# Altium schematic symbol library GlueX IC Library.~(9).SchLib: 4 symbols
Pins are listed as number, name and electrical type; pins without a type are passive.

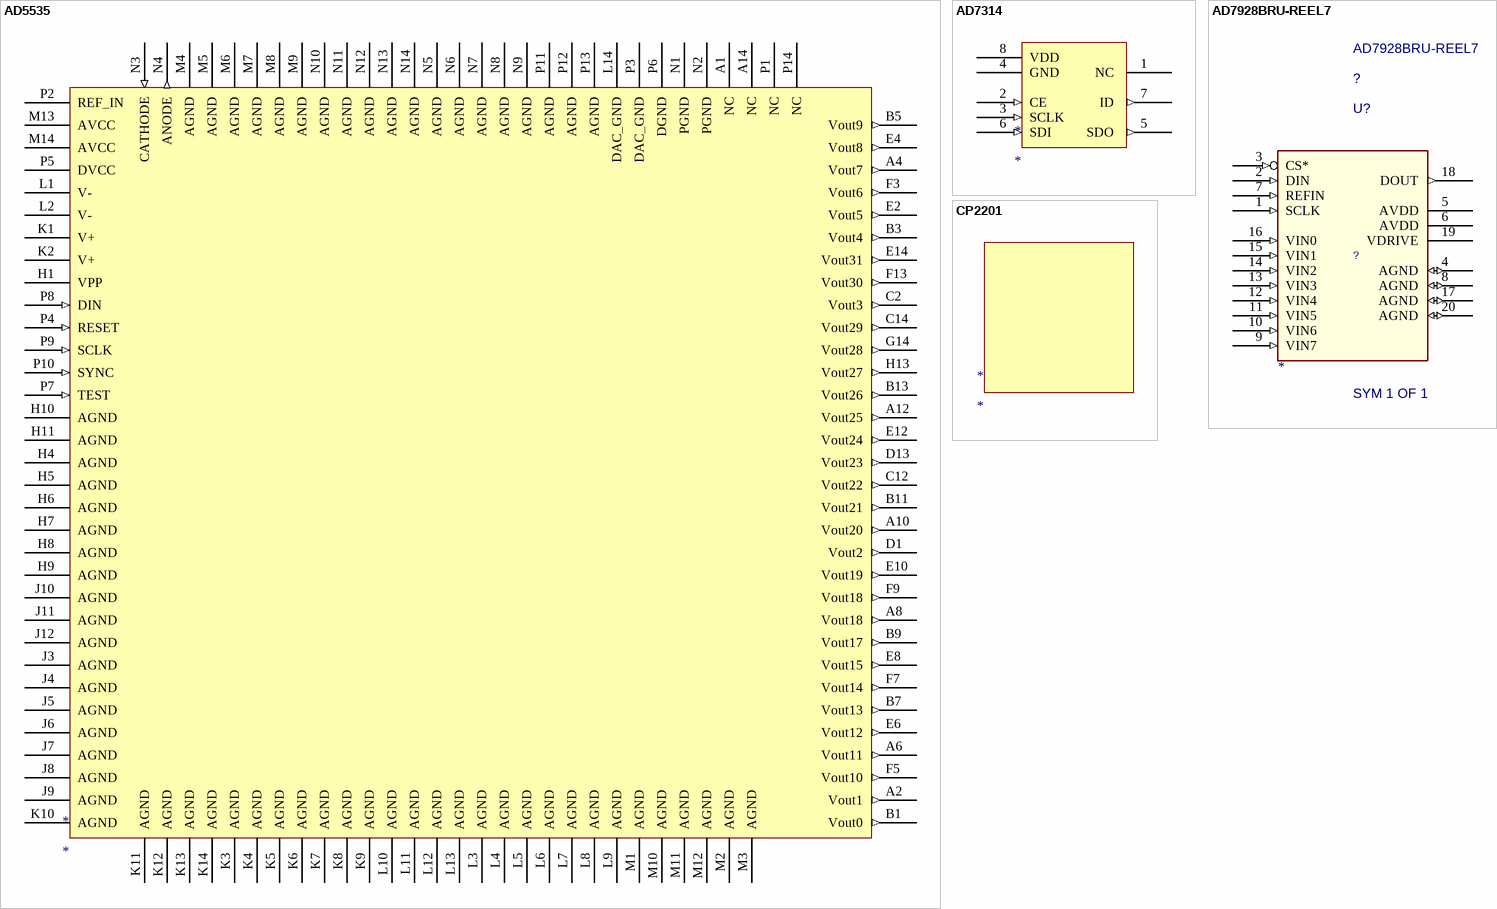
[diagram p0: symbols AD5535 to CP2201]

## AD5535
designator *
footprint BC-124
pins: A1 NC, A2 Vout1 (out), A4 Vout7 (out), A6 Vout11 (out), A8 Vout18 (out), A10 Vout20 (out), A12 Vout25 (out), A14 NC, B1 Vout0 (out), B3 Vout4 (out), B5 Vout9 (out), B7 Vout13 (out), B9 Vout17 (out), B11 Vout21 (out), B13 Vout26 (out), C2 Vout3 (out), C12 Vout22 (out), C14 Vout29 (out), D1 Vout2 (out), D13 Vout23 (out), E2 Vout5 (out), E4 Vout8 (out), E6 Vout12 (out), E8 Vout15 (out), E10 Vout19 (out), E12 Vout24 (out), E14 Vout31 (out), F3 Vout6 (out), F5 Vout10 (out), F7 Vout14 (out), F9 Vout18 (out), F13 Vout30 (out), G14 Vout28 (out), H1 VPP (power), H4 AGND, H5 AGND, H6 AGND, H7 AGND, H8 AGND, H9 AGND, H10 AGND, H11 AGND, H13 Vout27 (out), J3 AGND, J4 AGND, J5 AGND, J6 AGND, J7 AGND, J8 AGND, J9 AGND, J10 AGND, J11 AGND, J12 AGND, K1 V+ (power), K2 V+ (power), K3 AGND, K4 AGND, K5 AGND, K6 AGND, K7 AGND, K8 AGND, K9 AGND, K10 AGND, K11 AGND, K12 AGND, K13 AGND, K14 AGND, L1 V- (power), L2 V- (power), L3 AGND, L4 AGND, L5 AGND, L6 AGND, L7 AGND, L8 AGND, L9 AGND, L10 AGND, L11 AGND, L12 AGND, L13 AGND, L14 DAC_GND, M1 AGND, M2 AGND, M3 AGND, M4 AGND, M5 AGND, M6 AGND, M7 AGND, M8 AGND, M9 AGND, M10 AGND, M11 AGND, M12 AGND, M13 AVCC (power), M14 AVCC (power), N1 PGND, N2 PGND, N3 CATHODE (in), N4 ANODE (out), N5 AGND, N6 AGND, N7 AGND, N8 AGND, N9 AGND, N10 AGND, N11 AGND, N12 AGND, N13 AGND, N14 AGND, P1 NC, P2 REF_IN (hiz), P3 DAC_GND, P4 RESET (in), P5 DVCC (power), P6 DGND, P7 TEST (in), P8 DIN (in), P9 SCLK (in), P10 SYNC (in), P11 AGND, P12 AGND, P13 AGND, P14 NC

## AD7314
designator *
footprint RM-8
pins: 1 NC , 2 CE (in), 3 SCLK  (in), 4 GND  (power), 5 SDO  (out), 6 SDI  (in), 7 ID  (out), 8 VDD  (power)

## AD7928BRU-REEL7
designator U?  SymName: AD7928BRU-REEL7  SlotXofY: SYM 1 OF 1
footprint RU-20
pins: 1 SCLK (in), 2 DIN (in), 3 CS* (in), 4 AGND (io), 5 AVDD (power), 6 AVDD (power), 7 REFIN (in), 8 AGND (io), 9 VIN7 (in), 10 VIN6 (in), 11 VIN5 (in), 12 VIN4 (in), 13 VIN3 (in), 14 VIN2 (in), 15 VIN1 (in), 16 VIN0 (in), 17 AGND (io), 18 DOUT (out), 19 VDRIVE (power), 20 AGND (io)

## CP2201
designator *
footprint QFN-S28_N (28-Pin Saw Version Quad Flat No-Lead 0.65 mm Pitch, IPC Medium Density)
